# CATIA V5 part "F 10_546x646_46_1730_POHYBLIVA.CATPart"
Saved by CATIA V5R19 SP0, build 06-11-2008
Definition: F 10_546x646_46_1730_POHYBLIVA
Nomenclature: F 10_546x646_46_1730_POHYBLIVA
Description: PART--DESC
Material "Steel": density 7860 kg/m3, Young's modulus 2e+11 Pa, Poisson ratio 0.266, thermal expansion 1.17e-05 1/K
Bounding box of the stored display mesh (mm): x -323 to 323, y -298 to 298, z -324 to -278
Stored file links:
  G:\UTB\Kombinované\Bakalářská práce\Catia\FORMA\F 10_546x646_46_1730_POHYBLIVA.CATPart
  D:\Aplikace\CATIA\Nová složka\win_b64\startup\materials\Catalog.CATMaterial
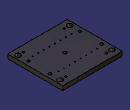
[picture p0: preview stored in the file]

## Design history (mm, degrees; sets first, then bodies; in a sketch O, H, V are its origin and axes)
Body1 "F 10_546646_46_1730" (main body)
  Solid1: solid without history
  Sketch1 on face of Solid1, origin (0, 0, -324), H (1, 0, 0), V (0, -1, 0)
    point P1 (0, 0)
    construction line L1 (300, 275) -> (300, -275)
    construction line L2 (300, -275) -> (-300, -275)
    construction line L3 (-300, -275) -> (-300, 275)
    construction line L4 (-300, 275) -> (300, 275)
    point P4 (-300, -275)
    reference intersected line E1 through (0, 0) direction (1, 0) from zx-plane
    reference intersected line E2 through (0, 0) direction (0, 1) from yz-plane
    distance L1 L3 = 600
    distance L2 L4 = 550
    vertical: L1 V, L3 V
    horizontal: L2 H, L4 H
    equidistance: L1 L3 P1, L2 L4 P1
    coincidence: P1 E1, P1 E2
  Sketch2 on face of Solid1, origin (-300, 275, -324), H (1, 0, 0), V (0, -1, 0)
    point P1 (0, 0)
    reference projected point E1 (0, 0) from Sketch1.P4
    coincidence: E1 P1
  Hole1: placed by Sketch2, at (-300, 275, -324) direction (0, 0, 1), diameter 6.647, depth 12, V-bottom angle 120, countersink depth 0.5, countersink angle 90, threaded "M8", thread diameter 8, thread depth 10, pitch 1.25
  UserPattern1: of Hole1, copies 4, at the points of Sketch1
  Sketch3 on face of Solid1, origin (-228.5122, -121.3732, -324), H (1, 0, 0), V (0, -1, 0)
    point P1 (18.5122, 18.6268)
    reference intersected line E1 through (0, -121.3732) direction (1, 0) from zx-plane
    reference intersected line E2 through (228.5122, 0) direction (0, 1) from yz-plane
    distance P1 E1 = 140
    distance P1 E2 = 210
  Hole2: placed by Sketch3, at (-210, -140, -324) direction (0, 0, 1), diameter 9, through (limit type 6), counterbore diameter 14, counterbore depth 5
  Chamfer1: length 1, angle 45, on face of Hole2; edge [face of Solid1 | face of Hole2]
  RectPattern1: of Hole2, Chamfer1, direction 1 instances 8, spacing 60, along X axis, direction 2 instances 2, spacing 280, along Y axis
  Sketch4 on face of Solid1, origin (-271.9962, -140.2613, -324), H (1, 0, 0), V (0, -1, 0)
    point P1 (-7.0038, -22.7613)
    reference intersected line E1 through (271.9962, 0) direction (0, 1) from yz-plane
    reference intersected line E2 through (0, -140.2613) direction (1, 0) from zx-plane
    distance P1 E1 = 279
    distance P1 E2 = 117.5
  Hole3: placed by Sketch4, at (-279, -117.5, -324) direction (0, 0, 1), diameter 30, through (limit type 6), counterbore diameter 36, counterbore depth 6
  Chamfer2: length 1, angle 45, on edge [face of Solid1 | face of Hole3]
  RectPattern2: of Hole3, Chamfer2, direction 1 instances 2, spacing 558, along X axis, direction 2 instances 2, spacing 235, along Y axis
  Sketch5 on face of Solid1, origin (0, 0, -320), H (1, 0, 0), V (0, -1, 0)
    point P1 (0, 0)
    reference intersected line E1 through (0, 0) direction (1, 0) from Plane1
    reference intersected line E2 through (0, 0) direction (0, 1) from Plane2
    coincidence: P1 E1, P1 E2
  Hole4: placed by Sketch5, at (0, 0, -320) direction (0, 0, 1), diameter 38, through (limit type 6)
  Plane1: stored without definition
  Plane2: stored without definition
  Sketch6 on face of Solid1, origin (0, 0, -320), H (1, 0, 0), V (0, -1, 0)
    point P1 (-26, 0)
    reference intersected line E1 through (0, 0) direction (1, 0) from Plane5
    reference intersected line E2 through (0, 0) direction (0, 1) from Plane6
    distance P1 E2 = 26
    coincidence: P1 E1
  Hole5: placed by Sketch6, at (-26, 0, -320) direction (0, 0, 1), diameter 4.917, depth 20, V-bottom angle 120, countersink depth 0.5, countersink angle 90, threaded "M6", thread diameter 6, thread depth 18, pitch 1
  CircPattern1: of Hole5, instances 2, angular step 180, axis from face of Hole4
  Plane3 to Plane6: stored without definition
  Sketch7 on face of Solid1, origin (-70.6705, 1.9523, -324), H (1, 0, 0), V (0, -1, 0)
    point P1 (18.6705, 1.9523)
    reference intersected line E1 through (0, 1.9523) direction (1, 0) from Plane7
    reference intersected line E2 through (70.6705, 0) direction (0, 1) from Plane8
    distance P1 E2 = 52
    coincidence: P1 E1
  Hole6: placed by Sketch7, at (-52, 0, -324) direction (0, 0, 1), diameter 4.134, depth 14, V-bottom angle 120, countersink depth 0.5, countersink angle 90, threaded "M5", thread diameter 5, thread depth 12, pitch 0.8
  CircPattern2: of Hole6, instances 2, angular step 180, axis from face of Solid1
  Plane7: stored without definition
  Plane8: stored without definition
  Sketch8 on face of Solid1, origin (-323, 11.1193, -307.8794), H (0, 1, 0), V (0, 0, -1)
    point P1 (-11.1193, -7.8794)
    reference intersected line E1 through (-11.1193, 0) direction (0, 1) from zx-plane
    reference projected line E2 (286.8807, -29.8794) -> (-309.1193, -29.8794) from edge [face of Solid1 | face of Solid1]
    distance P1 E2 = 22
    coincidence: P1 E1
  Hole7: placed by Sketch8, at (-323, 0, -300) direction (1, 0, 0), diameter 8.376, depth 20, V-bottom angle 120, countersink depth 1, countersink angle 90, threaded "M10", thread diameter 10, thread depth 18, pitch 1.5
  Sketch9 on face of Solid1, origin (-323, -56.363, -298.7494), H (0, 1, 0), V (0, 0, -1)
    point P1 (8.363, 1.2506)
    reference projected line E1 (354.363, -20.7494) -> (-241.637, -20.7494) from edge [face of Solid1 | face of Solid1]
    reference intersected line E2 through (56.363, 0) direction (0, 1) from zx-plane
    distance P1 E1 = 22
    distance P1 E2 = 48
  Hole8: placed by Sketch9, at (-323, -48, -300) direction (1, 0, 0), diameter 6.1, depth 7, V-bottom angle 120, countersink depth 1, countersink angle 90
